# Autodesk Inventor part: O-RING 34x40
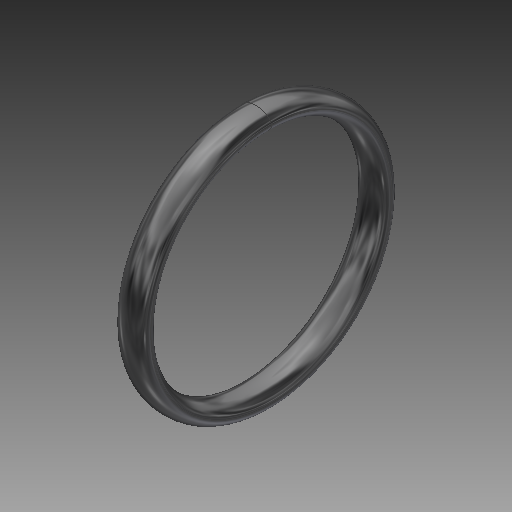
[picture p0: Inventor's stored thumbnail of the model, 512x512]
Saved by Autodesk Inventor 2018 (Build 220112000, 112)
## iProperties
Created: 2020-02
Part Number: O-RING 34x40
Material: 고무
Document SubType Name: Modeling
Designer: mduedu
Density: 1 g/cm^3
Appearance: 고무 - 검은색 - 버전 1.1
Author: mduedu
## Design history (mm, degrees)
sketch "스케치1"
  geometry: L1 (-3.29, 0)-(3.29, 0) reference; L2 (-2.35, 18.5)-(2.35, 18.5); L3 (0, 20)-(0, 17); 6 further points; 1 other entity
  constraints: 4 coincident, 4 end point, 2 horizontal, 2 midpoint, 1 vertical, 1 vertical alignment, 6 other
  dimensions: "d0" = 34 diameter of point (0, 17) L1; "d1" = 40 diameter of point (0, 20) L1; "d2" = 2.35 distance from line of point (2.35, 18.5) L3
revolve "회전1" sketch "스케치1" stored, may be unused: angle "d3" = 90 deg
node "솔리드1"
